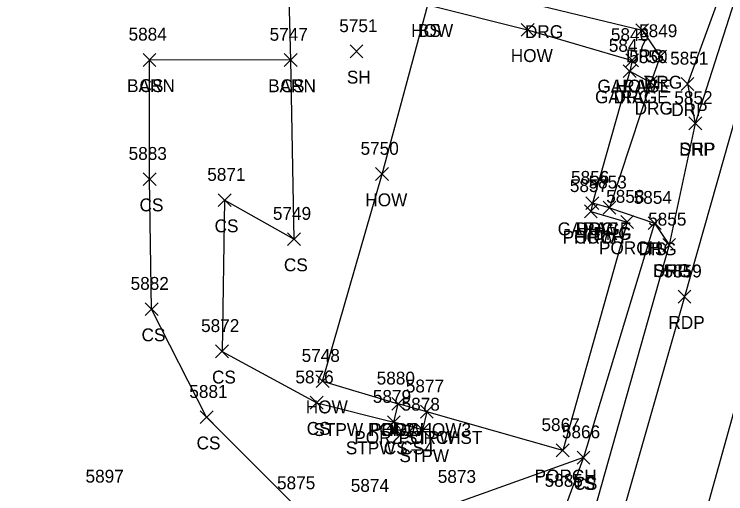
# Model space of a CAD drawing. Extents: x 1443912 to 1445411, y 621446 to 623693.
# Drawn here: x 1444563.4 to 1444674.1, y 622338.2 to 622412.7 of the extents above; entities that cross this region are included whole.
import ezdxf

# ---------------------------------------------------------------- set-up
doc = ezdxf.new("R2010")
doc.units = 0
for name, color, linetype in [('L_A', 7, 'Continuous'), ('L_I', 7, 'Continuous'), ('L_TIC', 7, 'Continuous'), ('LBC', 7, 'Continuous'), ('LBF', 7, 'Continuous'), ('LELB', 7, 'Continuous'), ('P_A', 7, 'Continuous'), ('P_I', 7, 'Continuous'), ('P_TIC', 7, 'Continuous'), ('PET', 7, 'Continuous'), ('PRC', 7, 'Continuous'), ('PSP', 7, 'Continuous'), ('R_A', 7, 'Continuous'), ('R_I', 7, 'Continuous'), ('R_TIC', 7, 'Continuous'), ('RDG', 7, 'Continuous'), ('RDP', 7, 'Continuous')]:
    doc.layers.add(name, color=color, linetype=linetype)

msp = doc.modelspace()

# ---------------------------------------------------------------- linework, layer by layer
at = {"layer": 'L_TIC'}
for points in [[(1444642.28, 622409.32), (1444644.28, 622411.32)], [(1444644.28, 622409.32), (1444642.28, 622411.32)], [(1444615.68, 622405.97), (1444617.68, 622407.97)], [(1444617.68, 622405.97), (1444615.68, 622407.97)], [(1444583.48, 622404.65), (1444585.48, 622406.65)], [(1444585.48, 622404.65), (1444583.48, 622406.65)], [(1444583.48, 622404.65), (1444585.48, 622406.65)], [(1444585.48, 622404.65), (1444583.48, 622406.65)], [(1444605.42, 622404.63), (1444607.42, 622406.63)], [(1444607.42, 622404.63), (1444605.42, 622406.63)], [(1444605.42, 622404.63), (1444607.42, 622406.63)], [(1444607.42, 622404.63), (1444605.42, 622406.63)], [(1444658.54, 622404.58), (1444660.54, 622406.58)], [(1444660.54, 622404.58), (1444658.54, 622406.58)], [(1444658.54, 622404.58), (1444660.54, 622406.58)], [(1444660.54, 622404.58), (1444658.54, 622406.58)], [(1444658.17, 622402.91), (1444660.17, 622404.91)], [(1444660.17, 622402.91), (1444658.17, 622404.91)], [(1444619.65, 622386.9), (1444621.65, 622388.9)], [(1444621.65, 622386.9), (1444619.65, 622388.9)], [(1444583.49, 622386.11), (1444585.49, 622388.11)], [(1444585.49, 622386.11), (1444583.49, 622388.11)], [(1444595.16, 622382.85), (1444597.16, 622384.85)], [(1444597.16, 622382.85), (1444595.16, 622384.85)], [(1444652.36, 622382.39), (1444654.36, 622384.39)], [(1444654.36, 622382.39), (1444652.36, 622384.39)], [(1444652.36, 622382.39), (1444654.36, 622384.39)], [(1444654.36, 622382.39), (1444652.36, 622384.39)], [(1444652.11, 622381.11), (1444654.11, 622383.11)], [(1444654.11, 622381.11), (1444652.11, 622383.11)], [(1444652.11, 622381.11), (1444654.11, 622383.11)], [(1444654.11, 622381.11), (1444652.11, 622383.11)], [(1444657.76, 622379.44), (1444659.76, 622381.44)], [(1444659.76, 622379.44), (1444657.76, 622381.44)], [(1444662.04, 622379.28), (1444664.04, 622381.28)], [(1444664.04, 622379.28), (1444662.04, 622381.28)], [(1444605.94, 622376.79), (1444607.94, 622378.79)], [(1444607.94, 622376.79), (1444605.94, 622378.79)], [(1444583.8, 622365.91), (1444585.8, 622367.91)], [(1444585.8, 622365.91), (1444583.8, 622367.91)], [(1444594.76, 622359.35), (1444596.76, 622361.35)], [(1444596.76, 622359.35), (1444594.76, 622361.35)], [(1444610.4, 622354.71), (1444612.4, 622356.71)], [(1444612.4, 622354.71), (1444610.4, 622356.71)], [(1444610.4, 622354.71), (1444612.4, 622356.71)], [(1444612.4, 622354.71), (1444610.4, 622356.71)], [(1444609.48, 622351.37), (1444611.48, 622353.37)], [(1444611.48, 622351.37), (1444609.48, 622353.37)], [(1444622.15, 622351.19), (1444624.15, 622353.19)], [(1444624.15, 622351.19), (1444622.15, 622353.19)], [(1444622.15, 622351.19), (1444624.15, 622353.19)], [(1444624.15, 622351.19), (1444622.15, 622353.19)], [(1444622.15, 622351.19), (1444624.15, 622353.19)], [(1444624.15, 622351.19), (1444622.15, 622353.19)], [(1444626.6, 622349.96), (1444628.6, 622351.96)], [(1444628.6, 622349.96), (1444626.6, 622351.96)], [(1444626.6, 622349.96), (1444628.6, 622351.96)], [(1444628.6, 622349.96), (1444626.6, 622351.96)], [(1444592.36, 622349.11), (1444594.36, 622351.11)], [(1444594.36, 622349.11), (1444592.36, 622351.11)], [(1444621.48, 622348.34), (1444623.48, 622350.34)], [(1444623.48, 622348.34), (1444621.48, 622350.34)], [(1444621.48, 622348.34), (1444623.48, 622350.34)], [(1444623.48, 622348.34), (1444621.48, 622350.34)], [(1444625.95, 622347.13), (1444627.95, 622349.13)], [(1444627.95, 622347.13), (1444625.95, 622349.13)], [(1444647.75, 622343.96), (1444649.75, 622345.96)], [(1444649.75, 622343.96), (1444647.75, 622345.96)], [(1444650.97, 622342.83), (1444652.97, 622344.83)], [(1444652.97, 622342.83), (1444650.97, 622344.83)], [(1444650.97, 622342.83), (1444652.97, 622344.83)], [(1444652.97, 622342.83), (1444650.97, 622344.83)]]:
    msp.add_lwpolyline(points, dxfattribs=at)
at = {"layer": 'LBC'}
for points in [[(1444574.04, 622421.62), (1444606, 622421.25), (1444606.42, 622405.63), (1444584.48, 622405.65)], [(1444611.4, 622355.71), (1444620.65, 622387.9), (1444627.78, 622414.22), (1444643.28, 622410.32), (1444659.54, 622405.58)], [(1444659.54, 622405.58), (1444659.17, 622403.91), (1444653.36, 622383.39)], [(1444653.36, 622383.39), (1444653.11, 622382.11)], [(1444611.4, 622355.71), (1444623.15, 622352.19)]]:
    msp.add_lwpolyline(points, dxfattribs=at)
at = {"layer": 'LBF'}
for points in [[(1444653.11, 622382.11), (1444658.76, 622380.44), (1444648.75, 622344.96), (1444627.6, 622350.96), (1444623.15, 622352.19)], [(1444627.6, 622350.96), (1444626.95, 622348.13), (1444622.48, 622349.34), (1444623.15, 622352.19)]]:
    msp.add_lwpolyline(points, dxfattribs=at)
at = {"layer": 'LELB'}
for points in [[(1444651.97, 622343.83), (1444632.57, 622336.9), (1444619.04, 622335.51), (1444607.57, 622335.91), (1444593.36, 622350.11), (1444584.8, 622366.91), (1444584.49, 622387.11), (1444584.48, 622405.65)], [(1444606.42, 622405.63), (1444606.94, 622377.79), (1444596.16, 622383.85), (1444595.76, 622360.35), (1444610.48, 622352.37), (1444622.48, 622349.34)], [(1444663.04, 622380.28), (1444651.97, 622343.83), (1444649.19, 622336.3), (1444642.49, 622317.47), (1444636.08, 622317.7)]]:
    msp.add_lwpolyline(points, dxfattribs=at)
at = {"layer": 'P_TIC'}
for points in [[(1444668.36, 622394.79), (1444670.36, 622396.79)], [(1444670.36, 622394.79), (1444668.36, 622396.79)], [(1444664.29, 622375.89), (1444666.29, 622377.89)], [(1444666.29, 622375.89), (1444664.29, 622377.89)], [(1444666.69, 622367.84), (1444668.69, 622369.84)], [(1444668.69, 622367.84), (1444666.69, 622369.84)]]:
    msp.add_lwpolyline(points, dxfattribs=at)
at = {"layer": 'PET'}
msp.add_lwpolyline([(1444707.78, 622511.05), (1444700.03, 622482.58), (1444691.73, 622453.67), (1444679.73, 622411.23), (1444667.69, 622368.84), (1444653.08, 622317.67), (1444637.74, 622256.92), (1444626.42, 622209.58), (1444619.02, 622182.67), (1444605.37, 622130.08), (1444589.4, 622078.61), (1444578.44, 622026.86), (1444565.52, 621990.05), (1444556.87, 621958.17), (1444542.16, 621907.74), (1444529.8, 621863.07), (1444511.99, 621799.88), (1444498.16, 621751.76), (1444483.13, 621697.3), (1444470.84, 621653.16), (1444463.41, 621627.34), (1444449.07, 621575.52), (1444430.26, 621508.83), (1444421.17, 621471.46)], dxfattribs=at)
at = {"layer": 'PRC'}
msp.add_lwpolyline([(1444846.73, 622950.74), (1444829.37, 622896.11), (1444814.12, 622840.53), (1444801.7, 622795.63), (1444790.08, 622753.54), (1444778.65, 622716.11), (1444769.12, 622683.18), (1444760.94, 622654.81), (1444750.77, 622619.03), (1444741.67, 622586.01), (1444729.73, 622541.23), (1444723.42, 622520.39), (1444711.77, 622478.97), (1444703.65, 622449.63), (1444691.66, 622407.43), (1444679.51, 622365.85), (1444664.93, 622313.64), (1444649.43, 622253.98), (1444637.04, 622206.21), (1444631.31, 622178.74), (1444618.32, 622127.38), (1444604.97, 622075.74)], dxfattribs=at)
at = {"layer": 'PSP'}
msp.add_lwpolyline([(1444708.02, 622525.06), (1444703.26, 622510.63), (1444694.99, 622483.8), (1444687.65, 622455.43), (1444679.42, 622427.15), (1444669.36, 622395.79), (1444665.29, 622376.89), (1444648.73, 622318.09), (1444646.34, 622310.05), (1444631.38, 622258.8), (1444618.63, 622212.47), (1444610.54, 622185.48), (1444596.17, 622132.46), (1444585.6, 622096.58)], dxfattribs=at)
at = {"layer": 'R_TIC'}
for points in [[(1444660.09, 622409.28), (1444662.09, 622411.28)], [(1444662.09, 622409.28), (1444660.09, 622411.28)], [(1444662.89, 622405.18), (1444664.89, 622407.18)], [(1444664.89, 622405.18), (1444662.89, 622407.18)], [(1444658.17, 622402.91), (1444660.17, 622404.91)], [(1444660.17, 622402.91), (1444658.17, 622404.91)], [(1444661.44, 622401.15), (1444663.44, 622403.15)], [(1444663.44, 622401.15), (1444661.44, 622403.15)], [(1444661.44, 622401.15), (1444663.44, 622403.15)], [(1444663.44, 622401.15), (1444661.44, 622403.15)], [(1444667.14, 622400.91), (1444669.14, 622402.91)], [(1444669.14, 622400.91), (1444667.14, 622402.91)], [(1444668.36, 622394.79), (1444670.36, 622396.79)], [(1444670.36, 622394.79), (1444668.36, 622396.79)], [(1444652.36, 622382.39), (1444654.36, 622384.39)], [(1444654.36, 622382.39), (1444652.36, 622384.39)], [(1444655.02, 622381.67), (1444657.02, 622383.67)], [(1444657.02, 622381.67), (1444655.02, 622383.67)], [(1444655.02, 622381.67), (1444657.02, 622383.67)], [(1444657.02, 622381.67), (1444655.02, 622383.67)], [(1444662.04, 622379.28), (1444664.04, 622381.28)], [(1444664.04, 622379.28), (1444662.04, 622381.28)], [(1444664.29, 622375.89), (1444666.29, 622377.89)], [(1444666.29, 622375.89), (1444664.29, 622377.89)]]:
    msp.add_lwpolyline(points, dxfattribs=at)
at = {"layer": 'RDG'}
for points in [[(1444675.89, 622423.07), (1444672.73, 622423.51), (1444646.83, 622427.21), (1444633.61, 622428.6), (1444632.37, 622419.67), (1444645.38, 622414.04), (1444661.09, 622410.28), (1444663.89, 622406.18), (1444662.44, 622402.15)], [(1444656.02, 622382.67), (1444663.04, 622380.28), (1444665.29, 622376.89)]]:
    msp.add_lwpolyline(points, dxfattribs=at)
at = {"layer": 'RDP'}
for points in [[(1444679.42, 622427.15), (1444675.89, 622423.07), (1444668.14, 622401.91), (1444669.36, 622395.79)], [(1444659.17, 622403.91), (1444662.44, 622402.15), (1444656.02, 622382.67), (1444653.36, 622383.39)]]:
    msp.add_lwpolyline(points, dxfattribs=at)

# ---------------------------------------------------------------- texts
at = {"layer": 'L_A'}
for s, p in [('HOW', (1444625.17, 622409.22)), ('BS', (1444626.22, 622409.22)), ('HOW', (1444640.67, 622405.32)), ('SH', (1444615.17, 622401.97)), ('BARN', (1444580.99, 622400.65)), ('CS', (1444582.92, 622400.65)), ('BARN', (1444602.93, 622400.63)), ('CS', (1444604.86, 622400.63)), ('GARAGE', (1444654.14, 622400.58)), ('HOW', (1444656.93, 622400.58)), ('GARAGE', (1444653.77, 622398.91)), ('HOW', (1444618.04, 622382.9)), ('CS', (1444582.93, 622382.11)), ('CS', (1444594.6, 622378.85)), ('GARAGE', (1444647.96, 622378.39)), ('HOW', (1444650.74, 622378.39)), ('PORCH', (1444648.74, 622377.11)), ('HOW', (1444650.5, 622377.11)), ('PORCH', (1444654.38, 622375.44)), ('TS', (1444661.45, 622375.28)), ('CS', (1444605.38, 622372.79)), ('CS', (1444583.24, 622361.91)), ('CS', (1444594.2, 622355.35)), ('HOW', (1444608.78, 622350.71)), ('HOW', (1444608.78, 622350.71)), ('CS', (1444608.92, 622347.37)), ('STPW POR2 HOW3', (1444609.97, 622347.19)), ('PORCH', (1444618.78, 622347.19)), ('HOW', (1444620.54, 622347.19)), ('POR2 STPW ST', (1444616.33, 622345.96)), ('PORCH', (1444623.22, 622345.96)), ('CS', (1444591.8, 622345.11)), ('STPW CS4', (1444615.01, 622344.34)), ('CS', (1444620.92, 622344.34)), ('STPW', (1444623.34, 622343.13)), ('PORCH', (1444644.37, 622339.96)), ('TS', (1444650.38, 622338.83)), ('CS', (1444650.41, 622338.83))]:
    msp.add_text(s, height=2, dxfattribs=at).set_placement(p)
at = {"layer": 'L_I'}
for s, p in [('5751', (1444613.99, 622409.97)), ('5884', (1444581.22, 622408.65)), ('5884', (1444581.22, 622408.65)), ('5747', (1444603.16, 622408.63)), ('5747', (1444603.16, 622408.63)), ('5846', (1444656.23, 622408.58)), ('5846', (1444656.23, 622408.58)), ('5847', (1444655.91, 622406.91)), ('5883', (1444581.23, 622390.11)), ('5750', (1444617.3, 622390.9)), ('5871', (1444593.46, 622386.85)), ('5856', (1444650.04, 622386.39)), ('5856', (1444650.04, 622386.39)), ('5857', (1444649.85, 622385.11)), ('5857', (1444649.85, 622385.11)), ('5858', (1444655.5, 622383.44)), ('5854', (1444659.78, 622383.28)), ('5749', (1444603.67, 622380.79)), ('5882', (1444581.54, 622369.91)), ('5872', (1444592.5, 622363.35)), ('5748', (1444608.14, 622358.71)), ('5748', (1444608.14, 622358.71)), ('5876', (1444607.17, 622355.37)), ('5880', (1444619.81, 622355.19)), ('5880', (1444619.81, 622355.19)), ('5880', (1444619.81, 622355.19)), ('5877', (1444624.34, 622353.96)), ('5877', (1444624.34, 622353.96)), ('5881', (1444590.67, 622353.11)), ('5879', (1444619.21, 622352.34)), ('5879', (1444619.21, 622352.34)), ('5878', (1444623.69, 622351.13)), ('5867', (1444645.44, 622347.96)), ('5866', (1444648.61, 622346.83)), ('5866', (1444648.61, 622346.83)), ('5897', (1444574.53, 622339.94)), ('5873', (1444629.31, 622339.9)), ('5873', (1444629.31, 622339.9)), ('5885', (1444645.93, 622339.3)), ('5875', (1444604.31, 622338.91)), ('5875', (1444604.31, 622338.91)), ('5874', (1444615.78, 622338.51)), ('5874', (1444615.78, 622338.51))]:
    msp.add_text(s, height=2, dxfattribs=at).set_placement(p)
at = {"layer": 'P_A'}
for s, p in [('SHP', (1444666.9, 622390.79)), ('SHP', (1444662.82, 622371.89)), ('RDP', (1444665.18, 622363.84))]:
    msp.add_text(s, height=2, dxfattribs=at).set_placement(p)
at = {"layer": 'P_I'}
for s, p in [('5852', (1444666.1, 622398.79)), ('5855', (1444662.03, 622379.89)), ('5859', (1444664.42, 622371.84))]:
    msp.add_text(s, height=2, dxfattribs=at).set_placement(p)
at = {"layer": 'R_A'}
for s, p in [('DRG', (1444642.87, 622409.04)), ('DRG', (1444658.58, 622405.28)), ('DRG', (1444661.38, 622401.18)), ('DRC', (1444656.66, 622398.91)), ('DRG', (1444659.93, 622397.15)), ('DRC', (1444659.93, 622397.15)), ('DRP', (1444665.63, 622396.91)), ('DRP', (1444666.85, 622390.79)), ('DRC', (1444650.85, 622378.39)), ('DRC', (1444653.51, 622377.67)), ('DRG', (1444653.51, 622377.67)), ('DRG', (1444660.53, 622375.28)), ('DRG', (1444662.78, 622371.89))]:
    msp.add_text(s, height=2, dxfattribs=at).set_placement(p)
at = {"layer": 'R_I'}
for s, p in [('5849', (1444660.62, 622409.18)), ('5847', (1444655.91, 622406.91)), ('5850', (1444659.09, 622405.15)), ('5850', (1444659.09, 622405.15)), ('5851', (1444665.45, 622404.91)), ('5852', (1444666.1, 622398.79)), ('5856', (1444650.04, 622386.39)), ('5853', (1444652.76, 622385.67)), ('5853', (1444652.76, 622385.67)), ('5854', (1444659.78, 622383.28)), ('5855', (1444662.03, 622379.89))]:
    msp.add_text(s, height=2, dxfattribs=at).set_placement(p)

doc.saveas('drawing.dxf')
